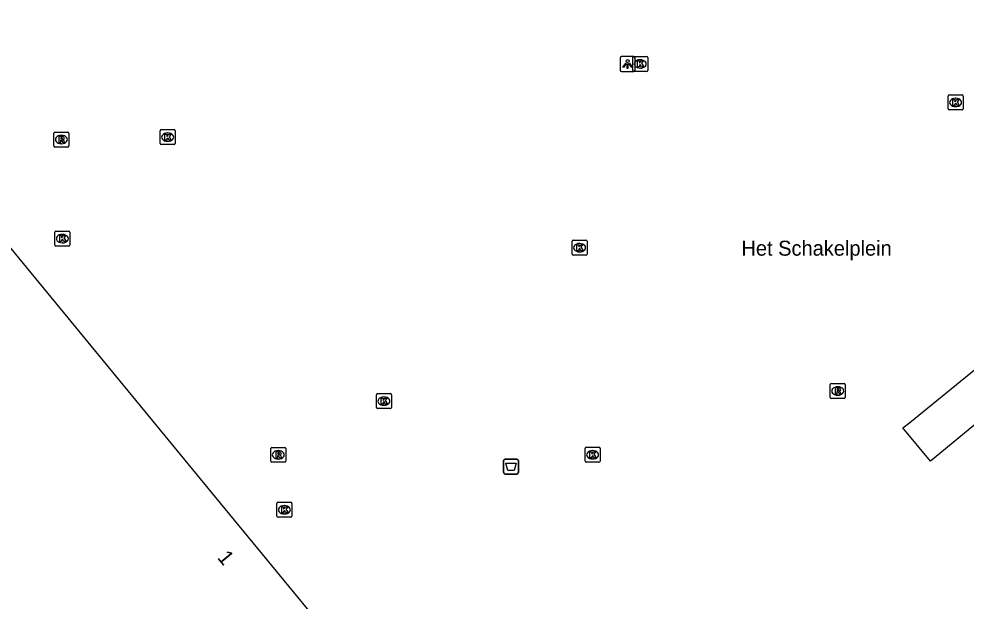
# Model space of a CAD drawing. Extents: x 156141 to 158132, y 385651 to 388399.
# Drawn here: x 157102.4 to 157165.7, y 386243.8 to 386282.7 of the extents above; entities that cross this region are included whole.
import ezdxf

# ---------------------------------------------------------------- set-up
doc = ezdxf.new("R2010")
doc.units = 0
for name, color, linetype in [('IMGEO_Afvalbak', 7, 'Continuous'), ('IMGEO_Haag', 7, 'Continuous'), ('IMGEO_Hek', 7, 'Continuous'), ('IMGEO_Kolk', 7, 'Continuous'), ('IMGEO_Lichtpunt', 7, 'Continuous'), ('IMGEO_Openbare_ruimte_label', 7, 'Continuous'), ('IMGEO_Pand', 7, 'Continuous'), ('IMGEO_Pand_nummerreeks', 7, 'Continuous'), ('IMGEO_Rioolput', 7, 'Continuous')]:
    doc.layers.add(name, color=color, linetype=linetype)

msp = doc.modelspace()

# ---------------------------------------------------------------- linework, layer by layer
at = {"layer": 'IMGEO_Afvalbak'}
for p, q in [((157134.788, 386252.43), (157134.788, 386253.23)), ((157134.788, 386253.23), (157134.788, 386252.43)), ((157134.888, 386253.33), (157135.678, 386253.33)), ((157135.678, 386253.33), (157134.888, 386253.33)), ((157135.778, 386253.23), (157135.778, 386252.43)), ((157135.778, 386252.43), (157135.778, 386253.23)), ((157135.678, 386252.33), (157134.888, 386252.33)), ((157134.888, 386252.33), (157135.678, 386252.33))]:
    msp.add_line(p, q, dxfattribs=at)
msp.add_lwpolyline([(157134.931, 386253.044), (157135.635, 386253.044), (157135.486, 386252.574), (157135.08, 386252.574), (157134.931, 386253.044)], dxfattribs=at)
for centre, start, end in [((157134.888, 386253.23), 90, 180), ((157134.888, 386253.23), 90, 180), ((157135.678, 386253.23), 0, 90), ((157135.678, 386253.23), 360, 90), ((157134.888, 386252.43), 180, 270), ((157134.888, 386252.43), 180, 270), ((157135.678, 386252.43), 270, 0), ((157135.678, 386252.43), 270, 0)]:
    msp.add_arc(centre, 0.1, start, end, dxfattribs=at)
at = {"layer": 'IMGEO_Haag'}
msp.add_lwpolyline([(157225.13, 386304.108), (157163.286, 386253.19), (157161.441, 386255.415), (157161.905, 386255.778), (157223.541, 386305.983)], dxfattribs=at)
at = {"layer": 'IMGEO_Hek'}
msp.add_lwpolyline([(157225.13, 386304.108), (157163.286, 386253.19)], dxfattribs=at)
at = {"layer": 'IMGEO_Kolk'}
for p, q in [((157143.411, 386279.285), (157143.411, 386280.137)), ((157143.486, 386280.211), (157144.338, 386280.211)), ((157143.899, 386279.991), (157143.924, 386279.991)), ((157144.412, 386280.137), (157144.412, 386279.285)), ((157144.338, 386279.211), (157143.486, 386279.211)), ((157143.922, 386279.431), (157143.897, 386279.431)), ((157164.474, 386276.713), (157164.474, 386277.565)), ((157164.549, 386277.639), (157165.401, 386277.639)), ((157164.962, 386277.419), (157164.987, 386277.419)), ((157165.475, 386277.565), (157165.475, 386276.713)), ((157165.401, 386276.639), (157164.549, 386276.639)), ((157164.985, 386276.859), (157164.96, 386276.859)), ((157111.931, 386275.324), (157112.783, 386275.324)), ((157111.856, 386274.398), (157111.856, 386275.25)), ((157112.344, 386275.104), (157112.369, 386275.104)), ((157112.857, 386275.25), (157112.857, 386274.398)), ((157112.783, 386274.324), (157111.931, 386274.324)), ((157112.367, 386274.544), (157112.342, 386274.544)), ((157104.825, 386267.622), (157104.825, 386268.474)), ((157104.9, 386268.548), (157105.752, 386268.548)), ((157105.826, 386268.474), (157105.826, 386267.622)), ((157105.336, 386267.768), (157105.311, 386267.768)), ((157105.313, 386268.328), (157105.338, 386268.328)), ((157139.362, 386267.015), (157139.362, 386267.867)), ((157139.437, 386267.941), (157140.289, 386267.941)), ((157139.85, 386267.721), (157139.875, 386267.721)), ((157140.363, 386267.867), (157140.363, 386267.015)), ((157105.752, 386267.548), (157104.9, 386267.548)), ((157139.873, 386267.161), (157139.848, 386267.161)), ((157140.289, 386266.941), (157139.437, 386266.941)), ((157126.295, 386256.772), (157126.295, 386257.624)), ((157126.37, 386257.698), (157127.222, 386257.698)), ((157127.296, 386257.624), (157127.296, 386256.772)), ((157126.783, 386257.478), (157126.808, 386257.478)), ((157127.222, 386256.698), (157126.37, 386256.698)), ((157126.806, 386256.918), (157126.781, 386256.918)), ((157140.232, 386253.187), (157140.232, 386254.039)), ((157140.307, 386254.113), (157141.159, 386254.113)), ((157140.72, 386253.893), (157140.745, 386253.893)), ((157141.233, 386254.039), (157141.233, 386253.187)), ((157140.743, 386253.333), (157140.718, 386253.333)), ((157141.159, 386253.113), (157140.307, 386253.113)), ((157119.652, 386249.514), (157119.652, 386250.366)), ((157119.727, 386250.44), (157120.579, 386250.44)), ((157120.14, 386250.22), (157120.165, 386250.22)), ((157120.653, 386250.366), (157120.653, 386249.514)), ((157120.579, 386249.44), (157119.727, 386249.44)), ((157120.163, 386249.66), (157120.138, 386249.66))]:
    msp.add_line(p, q, dxfattribs=at)
for points in [[(157143.411, 386279.285), (157143.411, 386280.137)], [(157143.486, 386280.211), (157144.338, 386280.211)], [(157143.732, 386279.911), (157143.855, 386279.911), (157143.855, 386279.76), (157143.985, 386279.911), (157144.149, 386279.911), (157144.003, 386279.76), (157144.156, 386279.511), (157144.004, 386279.511), (157143.919, 386279.675), (157143.855, 386279.608), (157143.855, 386279.511), (157143.732, 386279.511), (157143.732, 386279.911)], [(157144.412, 386280.137), (157144.412, 386279.285)], [(157144.338, 386279.211), (157143.486, 386279.211)], [(157164.474, 386276.713), (157164.474, 386277.565)], [(157164.549, 386277.639), (157165.401, 386277.639)], [(157164.795, 386277.339), (157164.918, 386277.339), (157164.918, 386277.188), (157165.048, 386277.339), (157165.212, 386277.339), (157165.066, 386277.188), (157165.219, 386276.939), (157165.067, 386276.939), (157164.982, 386277.103), (157164.918, 386277.036), (157164.918, 386276.939), (157164.795, 386276.939), (157164.795, 386277.339)], [(157165.475, 386277.565), (157165.475, 386276.713)], [(157165.401, 386276.639), (157164.549, 386276.639)], [(157111.931, 386275.324), (157112.783, 386275.324)], [(157111.856, 386274.398), (157111.856, 386275.25)], [(157112.177, 386275.024), (157112.3, 386275.024), (157112.3, 386274.873), (157112.43, 386275.024), (157112.594, 386275.024), (157112.448, 386274.873), (157112.601, 386274.624), (157112.449, 386274.624), (157112.364, 386274.788), (157112.3, 386274.721), (157112.3, 386274.624), (157112.177, 386274.624), (157112.177, 386275.024)], [(157112.857, 386275.25), (157112.857, 386274.398)], [(157112.783, 386274.324), (157111.931, 386274.324)], [(157104.825, 386267.622), (157104.825, 386268.474)], [(157104.9, 386268.548), (157105.752, 386268.548)], [(157105.826, 386268.474), (157105.826, 386267.622)], [(157105.146, 386268.248), (157105.269, 386268.248), (157105.269, 386268.097), (157105.399, 386268.248), (157105.563, 386268.248), (157105.417, 386268.097), (157105.57, 386267.848), (157105.418, 386267.848), (157105.333, 386268.012), (157105.269, 386267.945), (157105.269, 386267.848), (157105.146, 386267.848), (157105.146, 386268.248)], [(157139.362, 386267.015), (157139.362, 386267.867)], [(157139.437, 386267.941), (157140.289, 386267.941)], [(157140.363, 386267.867), (157140.363, 386267.015)], [(157105.752, 386267.548), (157104.9, 386267.548)], [(157139.683, 386267.641), (157139.806, 386267.641), (157139.806, 386267.49), (157139.936, 386267.641), (157140.1, 386267.641), (157139.954, 386267.49), (157140.107, 386267.241), (157139.955, 386267.241), (157139.87, 386267.405), (157139.806, 386267.338), (157139.806, 386267.241), (157139.683, 386267.241), (157139.683, 386267.641)], [(157140.289, 386266.941), (157139.437, 386266.941)], [(157126.295, 386256.772), (157126.295, 386257.624)], [(157126.37, 386257.698), (157127.222, 386257.698)], [(157127.296, 386257.624), (157127.296, 386256.772)], [(157126.616, 386257.398), (157126.739, 386257.398), (157126.739, 386257.247), (157126.869, 386257.398), (157127.033, 386257.398), (157126.887, 386257.247), (157127.04, 386256.998), (157126.888, 386256.998), (157126.803, 386257.162), (157126.739, 386257.095), (157126.739, 386256.998), (157126.616, 386256.998), (157126.616, 386257.398)], [(157127.222, 386256.698), (157126.37, 386256.698)], [(157140.232, 386253.187), (157140.232, 386254.039)], [(157140.307, 386254.113), (157141.159, 386254.113)], [(157140.553, 386253.813), (157140.676, 386253.813), (157140.676, 386253.662), (157140.806, 386253.813), (157140.97, 386253.813), (157140.824, 386253.662), (157140.977, 386253.413), (157140.825, 386253.413), (157140.74, 386253.577), (157140.676, 386253.51), (157140.676, 386253.413), (157140.553, 386253.413), (157140.553, 386253.813)], [(157141.233, 386254.039), (157141.233, 386253.187)], [(157141.159, 386253.113), (157140.307, 386253.113)], [(157119.652, 386249.514), (157119.652, 386250.366)], [(157119.727, 386250.44), (157120.579, 386250.44)], [(157119.973, 386250.14), (157120.096, 386250.14), (157120.096, 386249.989), (157120.226, 386250.14), (157120.39, 386250.14), (157120.244, 386249.989), (157120.397, 386249.74), (157120.245, 386249.74), (157120.16, 386249.904), (157120.096, 386249.837), (157120.096, 386249.74), (157119.973, 386249.74), (157119.973, 386250.14)], [(157120.653, 386250.366), (157120.653, 386249.514)], [(157120.579, 386249.44), (157119.727, 386249.44)]]:
    msp.add_lwpolyline(points, dxfattribs=at)
for centre, start, end in [((157143.488, 386280.135), 91.55205, 178.44795), ((157143.488, 386280.135), 91.55205, 178.44795), ((157144.336, 386280.135), 1.55205, 88.44795), ((157144.336, 386280.135), 1.55205, 88.44795), ((157143.488, 386279.287), 181.55205, 268.44795), ((157143.488, 386279.287), 181.55205, 268.44795), ((157144.336, 386279.287), 271.55205, 358.44795), ((157144.336, 386279.287), 271.55205, 358.44795), ((157164.551, 386277.563), 91.55205, 178.44795), ((157164.551, 386277.563), 91.55205, 178.44795), ((157165.399, 386277.563), 1.55205, 88.44795), ((157165.399, 386277.563), 1.55205, 88.44795), ((157164.551, 386276.715), 181.55205, 268.44795), ((157164.551, 386276.715), 181.55205, 268.44795), ((157165.399, 386276.715), 271.55205, 358.44795), ((157165.399, 386276.715), 271.55205, 358.44795), ((157111.933, 386275.248), 91.55205, 178.44795), ((157111.933, 386275.248), 91.55205, 178.44795), ((157112.781, 386275.248), 1.55205, 88.44795), ((157112.781, 386275.248), 1.55205, 88.44795), ((157111.933, 386274.4), 181.55205, 268.44795), ((157111.933, 386274.4), 181.55205, 268.44795), ((157112.781, 386274.4), 271.55205, 358.44795), ((157112.781, 386274.4), 271.55205, 358.44795), ((157104.902, 386268.472), 91.55205, 178.44795), ((157104.902, 386268.472), 91.55205, 178.44795), ((157105.75, 386268.472), 1.55205, 88.44795), ((157105.75, 386268.472), 1.55205, 88.44795), ((157139.439, 386267.865), 91.55205, 178.44795), ((157139.439, 386267.865), 91.55205, 178.44795), ((157140.287, 386267.865), 1.55205, 88.44795), ((157140.287, 386267.865), 1.55205, 88.44795), ((157104.902, 386267.624), 181.55205, 268.44795), ((157104.902, 386267.624), 181.55205, 268.44795), ((157105.75, 386267.624), 271.55205, 358.44795), ((157105.75, 386267.624), 271.55205, 358.44795), ((157139.439, 386267.017), 181.55205, 268.44795), ((157139.439, 386267.017), 181.55205, 268.44795), ((157140.287, 386267.017), 271.55205, 358.44795), ((157140.287, 386267.017), 271.55205, 358.44795), ((157126.372, 386257.622), 91.55205, 178.44795), ((157126.372, 386257.622), 91.55205, 178.44795), ((157127.22, 386257.622), 1.55205, 88.44795), ((157127.22, 386257.622), 1.55205, 88.44795), ((157126.372, 386256.774), 181.55205, 268.44795), ((157126.372, 386256.774), 181.55205, 268.44795), ((157127.22, 386256.774), 271.55205, 358.44795), ((157127.22, 386256.774), 271.55205, 358.44795), ((157140.309, 386254.037), 91.55205, 178.44795), ((157140.309, 386254.037), 91.55205, 178.44795), ((157141.157, 386254.037), 1.55205, 88.44795), ((157141.157, 386254.037), 1.55205, 88.44795), ((157140.309, 386253.189), 181.55205, 268.44795), ((157140.309, 386253.189), 181.55205, 268.44795), ((157141.157, 386253.189), 271.55205, 358.44795), ((157141.157, 386253.189), 271.55205, 358.44795), ((157119.729, 386250.364), 91.55205, 178.44795), ((157119.729, 386250.364), 91.55205, 178.44795), ((157120.577, 386250.364), 1.55205, 88.44795), ((157120.577, 386250.364), 1.55205, 88.44795), ((157119.729, 386249.516), 181.55205, 268.44795), ((157119.729, 386249.516), 181.55205, 268.44795), ((157120.577, 386249.516), 271.55205, 358.44795), ((157120.577, 386249.516), 271.55205, 358.44795)]:
    msp.add_arc(centre, 0.0765, start, end, dxfattribs=at)
for centre, major_axis, ratio, start_param, end_param in [((157143.898, 386279.711), (-0.387, 0.002), 0.722429, 4.712389, 7.853982), ((157143.923, 386279.711), (-0.39, 0.002), 0.717154, 1.570796, 4.712389), ((157164.961, 386277.139), (-0.387, 0.002), 0.722429, 4.712389, 7.853982), ((157164.986, 386277.139), (-0.39, 0.002), 0.717154, 1.570796, 4.712389), ((157112.343, 386274.824), (-0.387, 0.002), 0.722429, 4.712389, 7.853982), ((157112.368, 386274.824), (-0.39, 0.002), 0.717154, 1.570796, 4.712389), ((157105.312, 386268.048), (-0.387, 0.002), 0.722429, 4.712389, 7.853982), ((157105.337, 386268.048), (-0.39, 0.002), 0.717154, 1.570796, 4.712389), ((157139.849, 386267.441), (-0.387, 0.002), 0.722429, 4.712389, 7.853982), ((157139.874, 386267.441), (-0.39, 0.002), 0.717154, 1.570796, 4.712389), ((157126.782, 386257.198), (-0.387, 0.002), 0.722429, 4.712389, 7.853982), ((157126.807, 386257.198), (-0.39, 0.002), 0.717154, 1.570796, 4.712389), ((157140.719, 386253.613), (-0.387, 0.002), 0.722429, 4.712389, 7.853982), ((157140.744, 386253.613), (-0.39, 0.002), 0.717154, 1.570796, 4.712389), ((157120.139, 386249.94), (-0.387, 0.002), 0.722429, 4.712389, 7.853982), ((157120.164, 386249.94), (-0.39, 0.002), 0.717154, 1.570796, 4.712389)]:
    msp.add_ellipse(centre, major_axis=major_axis, ratio=ratio, start_param=start_param, end_param=end_param, dxfattribs=at)
at = {"layer": 'IMGEO_Lichtpunt'}
for p, q in [((157142.571, 386280.104), (157142.571, 386279.297)), ((157142.571, 386280.104), (157142.571, 386279.297)), ((157143.473, 386280.199), (157142.665, 386280.199)), ((157143.473, 386280.199), (157142.665, 386280.199)), ((157143.567, 386279.297), (157143.567, 386280.104)), ((157143.567, 386279.297), (157143.567, 386280.104)), ((157142.665, 386279.203), (157143.473, 386279.203)), ((157142.665, 386279.203), (157143.473, 386279.203))]:
    msp.add_line(p, q, dxfattribs=at)
for points in [[(157142.945, 386279.768), (157142.984, 386279.74), (157142.796, 386279.478), (157142.758, 386279.505), (157142.945, 386279.768)], [(157143.157, 386279.74), (157143.195, 386279.767), (157143.382, 386279.505), (157143.343, 386279.477), (157143.157, 386279.74)], [(157143.047, 386279.72), (157143.094, 386279.72), (157143.094, 386279.398), (157143.047, 386279.398), (157143.047, 386279.72)]]:
    msp.add_lwpolyline(points, dxfattribs=at)
msp.add_circle((157143.07, 386279.902), 0.0994, dxfattribs=at)
for centre, start, end in [((157142.665, 386280.104), 90, 180), ((157142.665, 386280.104), 90, 180), ((157143.473, 386280.104), 0, 90), ((157143.473, 386280.104), 0, 90), ((157142.665, 386279.297), 180, 270), ((157142.665, 386279.297), 180, 270), ((157143.473, 386279.297), 270, 0), ((157143.473, 386279.297), 270, 360)]:
    msp.add_arc(centre, 0.0946, start, end, dxfattribs=at)
at = {"layer": 'IMGEO_Pand'}
msp.add_lwpolyline([(157101.033, 386268.397), (157116.175, 386250), (157129.97, 386233.24), (157121.992, 386226.676), (157108.043, 386232.535), (157103.347, 386234.508), (157086.609, 386241.539), (157086.508, 386241.581), (157074.567, 386246.597)], dxfattribs=at)
at = {"layer": 'IMGEO_Rioolput'}
for p, q in [((157104.757, 386274.238), (157104.757, 386275.09)), ((157104.832, 386275.164), (157105.684, 386275.164)), ((157105.245, 386274.944), (157105.27, 386274.944)), ((157105.758, 386275.09), (157105.758, 386274.238)), ((157105.684, 386274.164), (157104.832, 386274.164)), ((157105.268, 386274.384), (157105.243, 386274.384)), ((157156.602, 386257.448), (157156.602, 386258.3)), ((157156.677, 386258.374), (157157.529, 386258.374)), ((157157.603, 386258.3), (157157.603, 386257.448)), ((157157.113, 386257.594), (157157.088, 386257.594)), ((157157.09, 386258.154), (157157.115, 386258.154)), ((157157.529, 386257.374), (157156.677, 386257.374)), ((157119.245, 386253.184), (157119.245, 386254.036)), ((157119.32, 386254.11), (157120.172, 386254.11)), ((157119.733, 386253.89), (157119.758, 386253.89)), ((157120.246, 386254.036), (157120.246, 386253.184)), ((157119.756, 386253.33), (157119.731, 386253.33)), ((157120.172, 386253.11), (157119.32, 386253.11))]:
    msp.add_line(p, q, dxfattribs=at)
for points in [[(157104.757, 386274.238), (157104.757, 386275.09)], [(157104.832, 386275.164), (157105.684, 386275.164)], [(157105.346, 386274.862), (157105.094, 386274.864), (157105.094, 386274.464)], [(157105.272, 386274.783), (157105.218, 386274.783), (157105.218, 386274.702)], [(157105.218, 386274.702), (157105.27, 386274.702)], [(157105.758, 386275.09), (157105.758, 386274.238)], [(157105.684, 386274.164), (157104.832, 386274.164)], [(157105.094, 386274.464), (157105.218, 386274.464), (157105.218, 386274.626), (157105.229, 386274.626)], [(157105.276, 386274.597), (157105.347, 386274.464), (157105.487, 386274.464), (157105.422, 386274.59)], [(157156.602, 386257.448), (157156.602, 386258.3)], [(157156.677, 386258.374), (157157.529, 386258.374)], [(157157.603, 386258.3), (157157.603, 386257.448)], [(157157.191, 386258.072), (157156.939, 386258.074), (157156.939, 386257.674)], [(157156.939, 386257.674), (157157.063, 386257.674), (157157.063, 386257.836), (157157.074, 386257.836)], [(157157.117, 386257.993), (157157.063, 386257.993), (157157.063, 386257.912)], [(157157.063, 386257.912), (157157.115, 386257.912)], [(157157.121, 386257.807), (157157.192, 386257.674), (157157.332, 386257.674), (157157.267, 386257.8)], [(157157.529, 386257.374), (157156.677, 386257.374)], [(157119.245, 386253.184), (157119.245, 386254.036)], [(157119.32, 386254.11), (157120.172, 386254.11)], [(157119.834, 386253.808), (157119.582, 386253.81), (157119.582, 386253.41)], [(157120.246, 386254.036), (157120.246, 386253.184)], [(157119.582, 386253.41), (157119.706, 386253.41), (157119.706, 386253.572), (157119.717, 386253.572)], [(157119.76, 386253.729), (157119.706, 386253.729), (157119.706, 386253.648)], [(157119.706, 386253.648), (157119.758, 386253.648)], [(157119.764, 386253.543), (157119.835, 386253.41), (157119.975, 386253.41), (157119.91, 386253.536)], [(157120.172, 386253.11), (157119.32, 386253.11)]]:
    msp.add_lwpolyline(points, dxfattribs=at)
for centre, radius, start, end in [((157104.834, 386275.088), 0.0765, 91.55205, 178.44795), ((157104.834, 386275.088), 0.0765, 91.55205, 178.44795), ((157105.254, 386274.891), 0.19, 274.7715, 282.96867), ((157105.278, 386274.687), 0.0964, 77.00612, 93.18647), ((157105.292, 386274.744), 0.0378, 276.66336, 79.67722), ((157105.345, 386274.752), 0.109, 350.36119, 89.41601), ((157105.343, 386274.752), 0.112, 277.58423, 350.98172), ((157105.682, 386275.088), 0.0765, 1.55205, 88.44795), ((157105.682, 386275.088), 0.0765, 1.55205, 88.44795), ((157104.834, 386274.24), 0.0765, 181.55205, 268.44795), ((157104.834, 386274.24), 0.0765, 181.55205, 268.44795), ((157105.228, 386274.573), 0.0533, 26.02933, 88.69889), ((157105.327, 386274.537), 0.108, 29.51342, 73.79051), ((157105.682, 386274.24), 0.0765, 271.55205, 358.44795), ((157105.682, 386274.24), 0.0765, 271.55205, 358.44795), ((157156.679, 386258.298), 0.0765, 91.55205, 178.44795), ((157156.679, 386258.298), 0.0765, 91.55205, 178.44795), ((157157.527, 386258.298), 0.0765, 1.55205, 88.44795), ((157157.527, 386258.298), 0.0765, 1.55205, 88.44795), ((157157.073, 386257.783), 0.0533, 26.02933, 88.69889), ((157157.099, 386258.101), 0.19, 274.7715, 282.96867), ((157157.123, 386257.897), 0.0964, 77.00612, 93.18647), ((157157.137, 386257.954), 0.0378, 276.66336, 79.67722), ((157157.19, 386257.962), 0.109, 350.36119, 89.41601), ((157157.188, 386257.962), 0.112, 277.58423, 350.98172), ((157157.172, 386257.747), 0.108, 29.51342, 73.79051), ((157156.679, 386257.45), 0.0765, 181.55205, 268.44795), ((157156.679, 386257.45), 0.0765, 181.55205, 268.44795), ((157157.527, 386257.45), 0.0765, 271.55205, 358.44795), ((157157.527, 386257.45), 0.0765, 271.55205, 358.44795), ((157119.322, 386254.034), 0.0765, 91.55205, 178.44795), ((157119.322, 386254.034), 0.0765, 91.55205, 178.44795), ((157119.833, 386253.698), 0.109, 350.36119, 89.41601), ((157120.17, 386254.034), 0.0765, 1.55205, 88.44795), ((157120.17, 386254.034), 0.0765, 1.55205, 88.44795), ((157119.322, 386253.186), 0.0765, 181.55205, 268.44795), ((157119.322, 386253.186), 0.0765, 181.55205, 268.44795), ((157119.716, 386253.519), 0.0533, 26.02933, 88.69889), ((157119.742, 386253.837), 0.19, 274.7715, 282.96867), ((157119.766, 386253.633), 0.0964, 77.00612, 93.18647), ((157119.78, 386253.69), 0.0378, 276.66336, 79.67722), ((157119.831, 386253.698), 0.112, 277.58423, 350.98172), ((157119.815, 386253.483), 0.108, 29.51342, 73.79051), ((157120.17, 386253.186), 0.0765, 271.55205, 358.44795), ((157120.17, 386253.186), 0.0765, 271.55205, 358.44795)]:
    msp.add_arc(centre, radius, start, end, dxfattribs=at)
for centre, major_axis, ratio, start_param, end_param in [((157105.244, 386274.664), (-0.387, 0.002), 0.722429, 4.712389, 7.853982), ((157105.269, 386274.664), (-0.39, 0.002), 0.717154, 1.570796, 4.712389), ((157157.089, 386257.874), (-0.387, 0.002), 0.722429, 4.712389, 7.853982), ((157157.114, 386257.874), (-0.39, 0.002), 0.717154, 1.570796, 4.712389), ((157119.732, 386253.61), (-0.387, 0.002), 0.722429, 4.712389, 7.853982), ((157119.757, 386253.61), (-0.39, 0.002), 0.717154, 1.570796, 4.712389)]:
    msp.add_ellipse(centre, major_axis=major_axis, ratio=ratio, start_param=start_param, end_param=end_param, dxfattribs=at)

# ---------------------------------------------------------------- texts
at = {"layer": 'IMGEO_Openbare_ruimte_label'}
msp.add_text('Het Schakelplein', height=1, dxfattribs=at).set_placement((157150.67, 386266.908))
at = {"layer": 'IMGEO_Pand_nummerreeks'}
msp.add_text('1', height=1, rotation=309.45939, dxfattribs=at).set_placement((157115.632, 386246.726))

doc.saveas('drawing.dxf')
